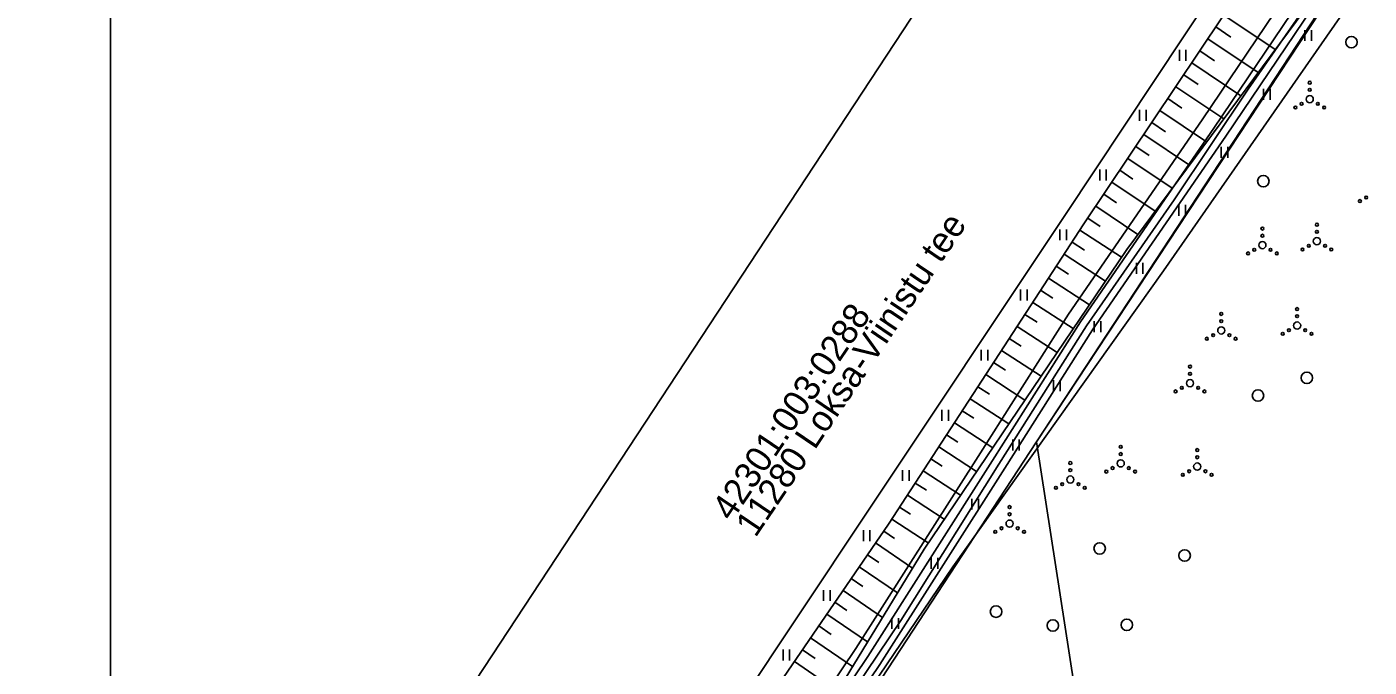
# Model space of a CAD drawing. Extents: x 599446 to 599962, y 6608194 to 6608886.
# Drawn here: x 599815.8 to 599909.2, y 6608728.6 to 6608773.2 of the extents above; entities that cross this region are included whole.
import ezdxf

# ---------------------------------------------------------------- set-up
doc = ezdxf.new("R2010")
doc.units = 0
for name, color, linetype in [('HALJASTUS', 7, 'Continuous'), ('KASUTUSALA', 7, 'Continuous'), ('MPKAABEL', 7, 'Continuous'), ('PIIR', 7, 'Continuous'), ('PR_SIDE', 7, 'Continuous'), ('RELJEEF', 7, 'Continuous'), ('TEE', 7, 'Continuous'), ('VORMISTUS_3', 7, 'Continuous')]:
    doc.layers.add(name, color=color, linetype=linetype)

msp = doc.modelspace()

# ---------------------------------------------------------------- linework, layer by layer
at = {"layer": 'HALJASTUS'}
for p, q in [((599904.735, 6608772.977), (599904.735, 6608772.216)), ((599905.19, 6608772.977), (599905.19, 6608772.216)), ((599896.012, 6608771.589), (599896.012, 6608770.828)), ((599896.467, 6608771.589), (599896.467, 6608770.828)), ((599901.867, 6608768.882), (599901.867, 6608768.121)), ((599902.322, 6608768.882), (599902.322, 6608768.121)), ((599893.237, 6608767.43), (599893.237, 6608766.669)), ((599893.692, 6608767.43), (599893.692, 6608766.669)), ((599898.917, 6608764.846), (599898.917, 6608764.084)), ((599899.372, 6608764.846), (599899.372, 6608764.084)), ((599890.462, 6608763.271), (599890.462, 6608762.51)), ((599890.917, 6608763.271), (599890.917, 6608762.51)), ((599895.967, 6608760.809), (599895.967, 6608760.048)), ((599896.422, 6608760.809), (599896.422, 6608760.048)), ((599887.693, 6608759.108), (599887.693, 6608758.346)), ((599888.148, 6608759.108), (599888.148, 6608758.346)), ((599893.017, 6608756.772), (599893.017, 6608756.011)), ((599893.472, 6608756.772), (599893.472, 6608756.011)), ((599884.958, 6608754.922), (599884.958, 6608754.161)), ((599885.413, 6608754.922), (599885.413, 6608754.161)), ((599890.083, 6608752.723), (599890.083, 6608751.962)), ((599890.538, 6608752.723), (599890.538, 6608751.962)), ((599882.223, 6608750.736), (599882.223, 6608749.975)), ((599882.679, 6608750.736), (599882.679, 6608749.975)), ((599887.247, 6608748.605), (599887.247, 6608747.844)), ((599887.702, 6608748.605), (599887.702, 6608747.844)), ((599879.489, 6608746.55), (599879.489, 6608745.789)), ((599879.944, 6608746.55), (599879.944, 6608745.789)), ((599884.412, 6608744.487), (599884.412, 6608743.726)), ((599884.867, 6608744.487), (599884.867, 6608743.726)), ((599876.754, 6608742.364), (599876.754, 6608741.603)), ((599877.209, 6608742.364), (599877.209, 6608741.603)), ((599881.576, 6608740.369), (599881.576, 6608739.608)), ((599882.031, 6608740.369), (599882.031, 6608739.608)), ((599874.019, 6608738.178), (599874.019, 6608737.417)), ((599874.474, 6608738.178), (599874.474, 6608737.417)), ((599878.741, 6608736.25), (599878.741, 6608735.489)), ((599879.196, 6608736.25), (599879.196, 6608735.489)), ((599871.251, 6608734.015), (599871.251, 6608733.254)), ((599871.706, 6608734.015), (599871.706, 6608733.254)), ((599876.004, 6608732.067), (599876.004, 6608731.306)), ((599876.459, 6608732.067), (599876.459, 6608731.306)), ((599868.434, 6608729.884), (599868.434, 6608729.123)), ((599868.889, 6608729.884), (599868.889, 6608729.123))]:
    msp.add_line(p, q, dxfattribs=at)
msp.add_lwpolyline([(599852.543, 6608691.108), (599853.603, 6608692.388), (599867.472, 6608716.753), (599880.24, 6608735.617), (599894.899, 6608756.219), (599910.836, 6608779.135), (599918.768, 6608792.661), (599928.933, 6608805.493), (599932.522, 6608815.935), (599934.355, 6608823.989), (599937.885, 6608823.395)], dxfattribs=at)
for centre, radius in [((599907.976, 6608772.131), 0.4), ((599905.076, 6608769.315), 0.1), ((599905.076, 6608768.815), 0.1), ((599904.511, 6608767.84), 0.1), ((599905.076, 6608768.165), 0.25), ((599905.641, 6608767.84), 0.1), ((599904.076, 6608767.59), 0.1), ((599906.076, 6608767.59), 0.1), ((599901.848, 6608762.464), 0.4), ((599908.568, 6608761.08), 0.1), ((599909.003, 6608761.33), 0.1), ((599905.576, 6608759.435), 0.1), ((599901.783, 6608759.164), 0.1), ((599901.783, 6608758.664), 0.1), ((599905.576, 6608758.285), 0.25), ((599905.576, 6608758.935), 0.1), ((599900.783, 6608757.439), 0.1), ((599901.218, 6608757.689), 0.1), ((599901.783, 6608758.014), 0.25), ((599902.348, 6608757.689), 0.1), ((599902.783, 6608757.439), 0.1), ((599904.576, 6608757.71), 0.1), ((599905.011, 6608757.96), 0.1), ((599906.141, 6608757.96), 0.1), ((599906.576, 6608757.71), 0.1), ((599898.921, 6608753.225), 0.1), ((599898.921, 6608752.725), 0.1), ((599904.196, 6608753.566), 0.1), ((599904.196, 6608753.066), 0.1), ((599898.356, 6608751.75), 0.1), ((599898.921, 6608752.075), 0.25), ((599899.486, 6608751.75), 0.1), ((599903.196, 6608751.841), 0.1), ((599903.631, 6608752.091), 0.1), ((599904.196, 6608752.416), 0.25), ((599904.761, 6608752.091), 0.1), ((599905.196, 6608751.841), 0.1), ((599897.921, 6608751.5), 0.1), ((599899.921, 6608751.5), 0.1), ((599896.746, 6608749.558), 0.1), ((599896.746, 6608749.058), 0.1), ((599904.878, 6608748.777), 0.4), ((599896.181, 6608748.083), 0.1), ((599896.746, 6608748.408), 0.25), ((599897.311, 6608748.083), 0.1), ((599895.746, 6608747.833), 0.1), ((599897.746, 6608747.833), 0.1), ((599901.476, 6608747.544), 0.4), ((599891.924, 6608743.978), 0.1), ((599891.924, 6608743.478), 0.1), ((599897.249, 6608743.754), 0.1), ((599888.42, 6608742.852), 0.1), ((599891.359, 6608742.503), 0.1), ((599891.924, 6608742.828), 0.25), ((599892.489, 6608742.503), 0.1), ((599897.249, 6608742.604), 0.25), ((599897.249, 6608743.254), 0.1), ((599888.42, 6608741.702), 0.25), ((599888.42, 6608742.352), 0.1), ((599890.924, 6608742.253), 0.1), ((599892.924, 6608742.253), 0.1), ((599896.249, 6608742.029), 0.1), ((599896.684, 6608742.279), 0.1), ((599897.814, 6608742.279), 0.1), ((599898.249, 6608742.029), 0.1), ((599887.42, 6608741.127), 0.1), ((599887.855, 6608741.377), 0.1), ((599888.985, 6608741.377), 0.1), ((599889.42, 6608741.127), 0.1), ((599884.197, 6608739.787), 0.1), ((599884.197, 6608738.637), 0.25), ((599884.197, 6608739.287), 0.1), ((599883.197, 6608738.062), 0.1), ((599883.632, 6608738.312), 0.1), ((599884.762, 6608738.312), 0.1), ((599885.197, 6608738.062), 0.1), ((599890.461, 6608736.91), 0.4), ((599896.372, 6608736.418), 0.4), ((599883.253, 6608732.513), 0.4), ((599887.207, 6608731.545), 0.4), ((599892.348, 6608731.597), 0.4)]:
    msp.add_circle(centre, radius, dxfattribs=at)
at = {"layer": 'KASUTUSALA'}
for points in [[(599826.263, 6608657.946), (599831.93, 6608665.812), (599837.125, 6608673.322), (599843.112, 6608683.081), (599848.477, 6608691.42), (599858.771, 6608707.697), (599865.927, 6608718.691), (599873.491, 6608729.939), (599882.17, 6608743.567), (599888.283, 6608753.216), (599897.588, 6608766.721), (599908.962, 6608783.581)], [(599910.63, 6608782.477), (599899.241, 6608765.594), (599889.951, 6608752.113), (599883.859, 6608742.495), (599875.165, 6608728.844), (599867.595, 6608717.587), (599860.455, 6608706.617), (599850.163, 6608690.344), (599844.805, 6608682.017), (599838.801, 6608672.229), (599833.564, 6608664.658), (599827.897, 6608656.791)]]:
    msp.add_lwpolyline(points, dxfattribs=at)
at = {"layer": 'MPKAABEL'}
msp.add_lwpolyline([(599850.041, 6608691.108), (599852.921, 6608695.67), (599859.863, 6608706.623), (599864.892, 6608714.388), (599871.031, 6608723.6), (599876.623, 6608731.904), (599883.438, 6608742.765), (599889.534, 6608752.388), (599895.653, 6608761.167), (599900.803, 6608768.873), (599907.301, 6608778.248), (599914.423, 6608789.11), (599920.723, 6608798.934), (599927.521, 6608809.514), (599934.42, 6608819.426), (599934.81, 6608819.904), (599941.024, 6608820.088)], dxfattribs=at)
at = {"layer": 'PIIR'}
for points in [[(599869.914, 6608848.608), (599880.68, 6608778.91), (599822.957, 6608691.108)], [(599822.957, 6608691.108), (599880.68, 6608778.91), (599912.29, 6608830.77), (599920.404, 6608848.608)], [(599945.397, 6608848.372), (599932.44, 6608820.83), (599935.43, 6608819.59), (599886.06, 6608744.32), (599851.222, 6608691.108)], [(599894.305, 6608691.108), (599886.06, 6608744.32), (599936.05, 6608820.15), (599945.397, 6608718.311)], [(599851.222, 6608691.108), (599886.06, 6608744.32), (599894.305, 6608691.108)]]:
    msp.add_lwpolyline(points, dxfattribs=at)
at = {"layer": 'PR_SIDE'}
msp.add_lwpolyline([(599780.528, 6608585.299), (599792.205, 6608602.287), (599793.2, 6608606.884), (599806.336, 6608627.013), (599816.965, 6608642.777), (599827.08, 6608657.369), (599832.748, 6608665.235), (599837.963, 6608672.776), (599843.959, 6608682.55), (599849.32, 6608690.883), (599859.613, 6608707.157), (599866.762, 6608718.139), (599874.329, 6608729.392), (599883.015, 6608743.032), (599889.118, 6608752.665), (599898.415, 6608766.158), (599909.797, 6608783.03), (599920.302, 6608799.204), (599927.105, 6608809.792), (599929.059, 6608812.663), (599931.154, 6608813.844)], dxfattribs=at)
at = {"layer": 'RELJEEF'}
for p, q in [((599899.091, 6608774.021), (599902.673, 6608771.623)), ((599898.535, 6608773.19), (599899.597, 6608772.479)), ((599897.422, 6608771.528), (599898.46, 6608770.833)), ((599897.978, 6608772.359), (599901.479, 6608770.015)), ((599896.866, 6608770.697), (599900.286, 6608768.407)), ((599896.309, 6608769.866), (599897.324, 6608769.187)), ((599895.753, 6608769.035), (599899.093, 6608766.799)), ((599895.197, 6608768.204), (599896.187, 6608767.542)), ((599894.64, 6608767.373), (599897.9, 6608765.191)), ((599894.084, 6608766.542), (599895.05, 6608765.896)), ((599893.528, 6608765.712), (599896.707, 6608763.583)), ((599892.415, 6608764.05), (599895.514, 6608761.975)), ((599892.971, 6608764.881), (599893.913, 6608764.25)), ((599891.859, 6608763.219), (599892.777, 6608762.604)), ((599891.302, 6608762.388), (599894.321, 6608760.367)), ((599890.746, 6608761.557), (599891.64, 6608760.958)), ((599890.19, 6608760.726), (599893.128, 6608758.758)), ((599889.633, 6608759.895), (599890.503, 6608759.313)), ((599889.083, 6608759.06), (599891.985, 6608757.171)), ((599888.537, 6608758.222), (599889.403, 6608757.658)), ((599887.446, 6608756.546), (599888.304, 6608755.988)), ((599887.992, 6608757.384), (599890.864, 6608755.514)), ((599886.901, 6608755.708), (599889.743, 6608753.858)), ((599886.355, 6608754.87), (599887.204, 6608754.317)), ((599885.81, 6608754.031), (599888.622, 6608752.201)), ((599885.264, 6608753.193), (599886.104, 6608752.647)), ((599884.719, 6608752.355), (599887.501, 6608750.544)), ((599884.173, 6608751.517), (599885.004, 6608750.977)), ((599883.628, 6608750.679), (599886.38, 6608748.888)), ((599883.082, 6608749.841), (599883.904, 6608749.306)), ((599881.992, 6608748.164), (599882.804, 6608747.636)), ((599882.537, 6608749.003), (599885.259, 6608747.231)), ((599881.446, 6608747.326), (599884.138, 6608745.574)), ((599880.901, 6608746.488), (599881.704, 6608745.966)), ((599880.355, 6608745.65), (599883.017, 6608743.917)), ((599879.81, 6608744.812), (599880.604, 6608744.295)), ((599879.264, 6608743.974), (599881.896, 6608742.261)), ((599878.719, 6608743.136), (599879.504, 6608742.625)), ((599878.173, 6608742.298), (599880.775, 6608740.604)), ((599877.628, 6608741.459), (599878.404, 6608740.954)), ((599876.537, 6608739.783), (599877.304, 6608739.284)), ((599877.082, 6608740.621), (599879.654, 6608738.947)), ((599875.991, 6608738.945), (599878.533, 6608737.291)), ((599875.435, 6608738.114), (599876.191, 6608737.597)), ((599874.87, 6608737.289), (599877.435, 6608735.533)), ((599874.305, 6608736.464), (599875.088, 6608735.928)), ((599873.74, 6608735.639), (599876.394, 6608733.822)), ((599873.175, 6608734.814), (599873.985, 6608734.26)), ((599872.045, 6608733.163), (599872.882, 6608732.591)), ((599872.61, 6608733.989), (599875.353, 6608732.111)), ((599871.481, 6608732.338), (599874.312, 6608730.4)), ((599870.916, 6608731.513), (599871.778, 6608730.922)), ((599870.351, 6608730.688), (599873.271, 6608728.689)), ((599869.786, 6608729.863), (599870.675, 6608729.254)), ((599869.221, 6608729.037), (599872.23, 6608726.978))]:
    msp.add_line(p, q, dxfattribs=at)
for points in [[(599846.39, 6608691.108), (599851.449, 6608698.533), (599862.058, 6608718.574), (599875.763, 6608738.594), (599889.363, 6608759.49), (599903.815, 6608781.077), (599913.596, 6608795.736), (599921.414, 6608809.252), (599932.358, 6608821.249), (599934.458, 6608821.117), (599936.807, 6608820.861)], [(599937.138, 6608819.453), (599934.765, 6608819.683), (599933.039, 6608818.51), (599925.288, 6608807.979), (599917.54, 6608793.773), (599908.877, 6608779.987), (599892.342, 6608757.699), (599878.246, 6608736.866), (599866.363, 6608717.336), (599851.986, 6608693.552), (599850.124, 6608691.108)]]:
    msp.add_lwpolyline(points, dxfattribs=at)
at = {"layer": 'TEE'}
msp.add_lwpolyline([(599841.837, 6608691.108), (599848.1, 6608700.538), (599860.763, 6608719.117), (599874.137, 6608739.213), (599888.038, 6608760.083), (599902.524, 6608781.928), (599911.341, 6608796.318), (599920.35, 6608810.81), (599927.039, 6608822.732), (599928.642, 6608823.673), (599930.628, 6608825.263), (599932.439, 6608825.461), (599934.848, 6608825.265)], dxfattribs=at)
at = {"layer": 'VORMISTUS_3'}
msp.add_lwpolyline([(599945.397, 6608691.108), (599821.647, 6608691.108), (599821.647, 6608848.608), (599945.397, 6608848.608)], close=True, dxfattribs=at)

# ---------------------------------------------------------------- texts
at = {"layer": 'PIIR'}
for s, p in [('11280 Loksa-Viinistu tee', (599866.515, 6608737.608)), ('42301:003:0288', (599864.858, 6608738.727))]:
    msp.add_text(s, height=1.8, rotation=55.97772, dxfattribs=at).set_placement(p)

doc.saveas('drawing.dxf')
